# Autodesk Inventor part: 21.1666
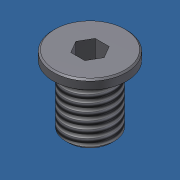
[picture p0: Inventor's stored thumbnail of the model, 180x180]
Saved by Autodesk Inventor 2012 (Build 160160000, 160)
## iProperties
Created: 2009-05
Part Number: 21.1666
Material: Stainless Steel
Document SubType Name: Modeling
Designer: Administrator
Mass: 4.75031 g
Surface Area: 5.96938 cm^2
Volume: 0.58791 cm^3
Density: 8.08 g/cm^3
Description: M8x10 Stainless Extra Low Head
Vendor: S
Author: Administrator
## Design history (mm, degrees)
sketch "Sketch1"
  geometry: C1 r 6 at (0, 0); 1 further point
  constraints: 1 centre point, 1 coincident
  dimensions: "d0" = 12 diameter of C1
extrude "Extrusion1" new body sketch "Sketch1" distance "d1" = 1.5; taper "d2" = 0 deg
sketch "Sketch2"
  geometry: C1 r 6 at (0, 0) reference; C2 r 4 at (0, 0)
  constraints: 1 centre point, 1 coincident
  dimensions: "d3" = 8 diameter of C2
extrude "Extrusion2" join sketch "Sketch2" distance "d4" = 10; taper "d5" = 0 deg
thread "Thread1" dims "d6" = 23, "d7" = 0
sketch "Sketch3"
  geometry: L1 (-1.155, 2)-(1.155, 2); L2 (1.155, 2)-(2.309, 0); L3 (2.309, 0)-(1.155, -2); L4 (1.155, -2)-(-1.155, -2); L5 (-1.155, -2)-(-2.309, 0); L6 (-2.309, 0)-(-1.155, 2); C1 r 6 at (0, 0) reference; 1 further point
  constraints: 12 end point, 3 parallel, 2 equal length, 2 horizontal alignment, 1 horizontal, 1 midpoint, 1 vertical alignment
  dimensions: "d8" = 120 deg angle of L2 L1; "d9" = 120 deg angle of L3 L2; "d10" = 4 distance between parallel lines of L3 L6
extrude "Extrusion3" cut sketch "Sketch3" distance "d11" = 5; taper "d12" = 0 deg
sketch "Sketch4"
  geometry: L1 (0, -5)-(2, -5) reference; L2 (2, -5)-(0, -5); L3 (0, -6.5)-(0.5, -6.5); L4 (0, -5)-(0, -6.5); L5 (0.915, -6.368)-(0.085, -6.632); A1 r 2.131 centre (-0.146, -4.47) between (0.164, -6.578) and (0.819, -6.369); 1 further point
  constraints: 8 end point, 2 midpoint, 1 centre point, 1 collinear, 1 parallel, 1 perpendicular, 1 point on circle, 4 other
  dimensions: "d13" = 1.5 distance of L1.start L3.start; "d14" = 0.5 distance of L3.start L3.end
revolve "Revolution1" sketch "Sketch4" stored, may be unused: angle "d15" = 90 deg
chamfer "Chamfer1" distance "d16" = 0.25; stored, may be unused: second distance "d17" = 2, angle "d18" = 45 deg
chamfer "Chamfer2" distance "d19" = 0.5; stored, may be unused: second distance "d20" = 2, angle "d21" = 45 deg
body "Solid1"
